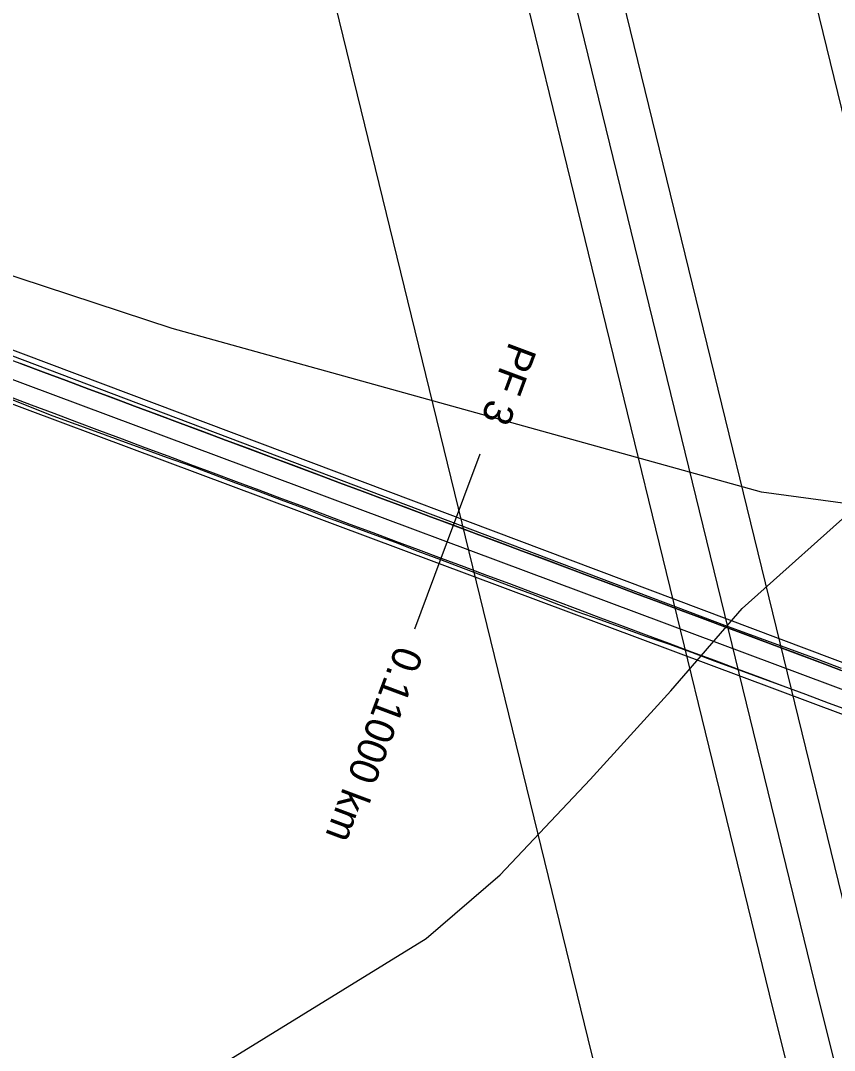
# Model space of a CAD drawing. Extents: x -555887 to -552101, y -1100251 to -1096546.
# Drawn here: x -553613.1 to -553543.4, y -1097330.6 to -1097242.4 of the extents above; entities that cross this region are included whole.
import ezdxf

# ---------------------------------------------------------------- set-up
doc = ezdxf.new("R2010")
doc.units = 0
for name, color, linetype in [('07_OCH_P A POPISY TI', 7, 'Continuous'), ('07_PLYNOVOD', 7, 'Continuous'), ('PARCELY_cesty', 7, 'Continuous'), ('POLYGONY_SITUACE_PF', 7, 'Continuous'), ('POLYGONY_SITUACE_PF_POPISY', 7, 'Continuous'), ('POLYGONY_SITUACE_PO', 7, 'Continuous'), ('vrstevnice', 7, 'Continuous'), ('ZSST', 7, 'Continuous')]:
    doc.layers.add(name, color=color, linetype=linetype)

msp = doc.modelspace()

# ---------------------------------------------------------------- linework, layer by layer
at = {"layer": '07_OCH_P A POPISY TI'}
for points in [[(-553574.217, -1097120.442), (-553565.588, -1097155.535), (-553546.885, -1097232.999), (-553525.624, -1097320.013), (-553504.501, -1097404.573), (-553504.455, -1097404.754), (-553494.227, -1097444.768), (-553477.771, -1097515.856), (-553477.697, -1097516.109), (-553477.381, -1097517.195), (-553476.998, -1097519.425), (-553476.868, -1097521.684), (-553476.994, -1097523.943), (-553477.184, -1097525.058), (-553488.78, -1097593.146), (-553503.72, -1097682.074)], [(-553589.763, -1097124.224), (-553581.134, -1097159.323), (-553562.433, -1097236.776), (-553541.157, -1097323.851), (-553520.012, -1097408.499), (-553519.955, -1097408.722), (-553509.773, -1097448.554), (-553493.258, -1097519.899), (-553493.059, -1097520.582), (-553492.932, -1097521.018), (-553492.88, -1097521.924), (-553492.957, -1097522.372), (-553504.556, -1097590.477), (-553519.48, -1097679.311)], [(-553527.36, -1097677.929), (-553512.444, -1097589.143), (-553500.998, -1097521.936), (-553501.002, -1097521.921), (-553517.547, -1097450.446), (-553527.705, -1097410.706), (-553527.768, -1097410.461), (-553548.923, -1097325.769), (-553570.207, -1097238.664), (-553588.906, -1097161.217), (-553597.537, -1097126.116)], [(-553543.12, -1097675.166), (-553528.22, -1097586.474), (-553517.31, -1097522.417), (-553533.093, -1097454.232), (-553543.205, -1097414.674), (-553543.279, -1097414.387), (-553564.456, -1097329.607), (-553585.755, -1097242.441), (-553604.452, -1097165.005), (-553613.083, -1097129.898)]]:
    msp.add_lwpolyline(points, dxfattribs=at)
at = {"layer": '07_PLYNOVOD'}
msp.add_lwpolyline([(-553585.25, -1098028.34), (-553568.13, -1097932.52), (-553553.96, -1097851.86), (-553539.25, -1097765.27), (-553523.42, -1097678.62), (-553508.5, -1097589.81), (-553496.9, -1097521.7), (-553497.13, -1097520.91), (-553513.66, -1097449.5), (-553523.83, -1097409.714), (-553523.89, -1097409.48), (-553545.04, -1097324.81), (-553566.32, -1097237.72), (-553585.02, -1097160.27), (-553593.65, -1097125.17), (-553614.64, -1097037.99), (-553634.86, -1096953.32), (-553647.662, -1096902.456)], dxfattribs=at)
at = {"layer": 'PARCELY_cesty'}
msp.add_line((-553673.4, -1097248.15), (-553478.332, -1097321.582), dxfattribs=at)
msp.add_lwpolyline([(-553665.731, -1097263.939), (-553661.91, -1097259.75), (-553656.336, -1097259.353), (-553478.346, -1097325.848)], dxfattribs=at)
at = {"layer": 'POLYGONY_SITUACE_PF'}
for p, q in [((-553573.729, -1097279.527), (-553576.529, -1097287.021)), ((-553576.529, -1097287.021), (-553579.33, -1097294.515))]:
    msp.add_line(p, q, dxfattribs=at)
at = {"layer": 'POLYGONY_SITUACE_PO'}
for p, q in [((-553675.709, -1097247.696), (-553552.545, -1097294.259)), ((-553679.807, -1097248.45), (-553478.542, -1097323.639)), ((-553673.735, -1097249.093), (-553501.847, -1097313.329)), ((-553613.083, -1097271.759), (-553611.132, -1097272.489)), ((-553611.132, -1097272.489), (-553613.083, -1097271.759)), ((-553611.132, -1097272.489), (-553609.18, -1097273.218)), ((-553609.18, -1097273.218), (-553611.132, -1097272.489)), ((-553609.18, -1097273.218), (-553607.229, -1097273.947)), ((-553607.229, -1097273.947), (-553609.18, -1097273.218)), ((-553607.229, -1097273.947), (-553605.277, -1097274.676)), ((-553605.277, -1097274.676), (-553607.229, -1097273.947)), ((-553614.185, -1097274.707), (-553612.249, -1097275.478)), ((-553614.133, -1097274.569), (-553612.182, -1097275.299)), ((-553614.133, -1097274.569), (-553612.182, -1097275.299)), ((-553605.277, -1097274.676), (-553603.325, -1097275.406)), ((-553603.325, -1097275.406), (-553605.277, -1097274.676)), ((-553612.249, -1097275.478), (-553610.307, -1097276.234)), ((-553612.182, -1097275.299), (-553610.23, -1097276.028)), ((-553612.182, -1097275.299), (-553610.23, -1097276.028)), ((-553603.325, -1097275.406), (-553601.374, -1097276.135)), ((-553601.374, -1097276.135), (-553603.325, -1097275.406)), ((-553610.307, -1097276.234), (-553608.349, -1097276.947)), ((-553610.23, -1097276.028), (-553608.279, -1097276.757)), ((-553610.23, -1097276.028), (-553608.279, -1097276.757)), ((-553601.374, -1097276.135), (-553599.422, -1097276.864)), ((-553599.422, -1097276.864), (-553601.374, -1097276.135)), ((-553608.349, -1097276.947), (-553606.392, -1097277.659)), ((-553608.279, -1097276.757), (-553606.327, -1097277.487)), ((-553608.279, -1097276.757), (-553606.327, -1097277.487)), ((-553606.327, -1097277.487), (-553604.376, -1097278.216)), ((-553606.327, -1097277.487), (-553604.376, -1097278.216)), ((-553599.422, -1097276.864), (-553597.471, -1097277.594)), ((-553597.471, -1097277.594), (-553599.422, -1097276.864)), ((-553606.392, -1097277.659), (-553604.436, -1097278.376)), ((-553604.436, -1097278.376), (-553602.48, -1097279.093)), ((-553604.376, -1097278.216), (-553602.424, -1097278.945)), ((-553604.376, -1097278.216), (-553602.424, -1097278.945)), ((-553597.471, -1097277.594), (-553595.519, -1097278.323)), ((-553595.519, -1097278.323), (-553597.471, -1097277.594)), ((-553595.519, -1097278.323), (-553593.568, -1097279.052)), ((-553593.568, -1097279.052), (-553595.519, -1097278.323)), ((-553602.48, -1097279.093), (-553600.523, -1097279.808)), ((-553602.424, -1097278.945), (-553600.473, -1097279.675)), ((-553602.424, -1097278.945), (-553600.473, -1097279.675)), ((-553593.568, -1097279.052), (-553591.616, -1097279.782)), ((-553591.616, -1097279.782), (-553593.568, -1097279.052)), ((-553600.523, -1097279.808), (-553598.553, -1097280.49)), ((-553600.473, -1097279.675), (-553598.521, -1097280.404)), ((-553600.473, -1097279.675), (-553598.521, -1097280.404)), ((-553591.616, -1097279.782), (-553589.665, -1097280.511)), ((-553589.665, -1097280.511), (-553591.616, -1097279.782)), ((-553598.553, -1097280.49), (-553596.608, -1097281.236)), ((-553598.521, -1097280.404), (-553596.57, -1097281.133)), ((-553598.521, -1097280.404), (-553596.57, -1097281.133)), ((-553589.665, -1097280.511), (-553587.713, -1097281.24)), ((-553587.713, -1097281.24), (-553589.665, -1097280.511)), ((-553596.608, -1097281.236), (-553594.658, -1097281.968)), ((-553596.57, -1097281.133), (-553594.618, -1097281.862)), ((-553596.57, -1097281.133), (-553594.618, -1097281.862)), ((-553594.618, -1097281.862), (-553592.667, -1097282.592)), ((-553594.618, -1097281.862), (-553592.667, -1097282.592)), ((-553587.713, -1097281.24), (-553585.762, -1097281.969)), ((-553585.762, -1097281.969), (-553587.713, -1097281.24)), ((-553594.658, -1097281.968), (-553592.704, -1097282.692)), ((-553592.704, -1097282.692), (-553590.756, -1097283.43)), ((-553592.667, -1097282.592), (-553590.715, -1097283.321)), ((-553592.667, -1097282.592), (-553590.715, -1097283.321)), ((-553585.762, -1097281.969), (-553583.81, -1097282.699)), ((-553583.81, -1097282.699), (-553585.762, -1097281.969)), ((-553583.81, -1097282.699), (-553581.859, -1097283.428)), ((-553581.859, -1097283.428), (-553583.81, -1097282.699)), ((-553590.756, -1097283.43), (-553588.804, -1097284.158)), ((-553590.715, -1097283.321), (-553588.764, -1097284.05)), ((-553590.715, -1097283.321), (-553588.764, -1097284.05)), ((-553581.859, -1097283.428), (-553579.907, -1097284.157)), ((-553579.907, -1097284.157), (-553581.859, -1097283.428)), ((-553588.804, -1097284.158), (-553586.862, -1097284.913)), ((-553588.764, -1097284.05), (-553586.812, -1097284.78)), ((-553588.764, -1097284.05), (-553586.812, -1097284.78)), ((-553579.907, -1097284.157), (-553577.956, -1097284.887)), ((-553577.956, -1097284.887), (-553579.907, -1097284.157)), ((-553586.862, -1097284.913), (-553584.908, -1097285.636)), ((-553586.812, -1097284.78), (-553584.861, -1097285.509)), ((-553586.812, -1097284.78), (-553584.861, -1097285.509)), ((-553577.956, -1097284.887), (-553576.004, -1097285.616)), ((-553576.004, -1097285.616), (-553577.956, -1097284.887)), ((-553584.908, -1097285.636), (-553582.951, -1097286.35)), ((-553584.861, -1097285.509), (-553582.909, -1097286.238)), ((-553584.861, -1097285.509), (-553582.909, -1097286.238)), ((-553582.909, -1097286.238), (-553580.958, -1097286.967)), ((-553582.909, -1097286.238), (-553580.958, -1097286.967)), ((-553576.004, -1097285.616), (-553574.053, -1097286.345)), ((-553574.053, -1097286.345), (-553576.004, -1097285.616)), ((-553582.951, -1097286.35), (-553580.995, -1097287.067)), ((-553580.995, -1097287.067), (-553579.057, -1097287.832)), ((-553580.958, -1097286.967), (-553579.006, -1097287.697)), ((-553580.958, -1097286.967), (-553579.006, -1097287.697)), ((-553574.053, -1097286.345), (-553572.101, -1097287.074)), ((-553572.101, -1097287.074), (-553574.053, -1097286.345)), ((-553572.101, -1097287.074), (-553570.15, -1097287.804)), ((-553570.15, -1097287.804), (-553572.101, -1097287.074)), ((-553579.057, -1097287.832), (-553577.104, -1097288.558)), ((-553579.006, -1097287.697), (-553577.054, -1097288.426)), ((-553579.006, -1097287.697), (-553577.054, -1097288.426)), ((-553570.15, -1097287.804), (-553568.198, -1097288.533)), ((-553568.198, -1097288.533), (-553570.15, -1097287.804)), ((-553577.104, -1097288.558), (-553575.151, -1097289.283)), ((-553577.054, -1097288.426), (-553575.103, -1097289.155)), ((-553577.054, -1097288.426), (-553575.103, -1097289.155)), ((-553568.198, -1097288.533), (-553566.247, -1097289.262)), ((-553566.247, -1097289.262), (-553568.198, -1097288.533)), ((-553575.151, -1097289.283), (-553573.203, -1097290.022)), ((-553575.103, -1097289.155), (-553573.151, -1097289.885)), ((-553575.103, -1097289.155), (-553573.151, -1097289.885)), ((-553566.247, -1097289.262), (-553564.295, -1097289.992)), ((-553564.295, -1097289.992), (-553566.247, -1097289.262)), ((-553573.203, -1097290.022), (-553571.263, -1097290.783)), ((-553573.151, -1097289.885), (-553571.2, -1097290.614)), ((-553573.151, -1097289.885), (-553571.2, -1097290.614)), ((-553571.2, -1097290.614), (-553569.248, -1097291.343)), ((-553571.2, -1097290.614), (-553569.248, -1097291.343)), ((-553564.295, -1097289.992), (-553562.344, -1097290.721)), ((-553562.344, -1097290.721), (-553564.295, -1097289.992)), ((-553562.344, -1097290.721), (-553560.392, -1097291.45)), ((-553560.392, -1097291.45), (-553562.344, -1097290.721)), ((-553571.263, -1097290.783), (-553569.304, -1097291.492)), ((-553569.304, -1097291.492), (-553567.365, -1097292.256)), ((-553569.248, -1097291.343), (-553567.297, -1097292.073)), ((-553569.248, -1097291.343), (-553567.297, -1097292.073)), ((-553560.392, -1097291.45), (-553558.441, -1097292.18)), ((-553558.441, -1097292.18), (-553560.392, -1097291.45)), ((-553567.365, -1097292.256), (-553565.422, -1097293.008)), ((-553567.297, -1097292.073), (-553565.345, -1097292.802)), ((-553567.297, -1097292.073), (-553565.345, -1097292.802)), ((-553558.441, -1097292.18), (-553556.489, -1097292.909)), ((-553556.489, -1097292.909), (-553558.441, -1097292.18)), ((-553565.422, -1097293.008), (-553563.455, -1097293.695)), ((-553565.345, -1097292.802), (-553563.394, -1097293.531)), ((-553565.345, -1097292.802), (-553563.394, -1097293.531)), ((-553556.489, -1097292.909), (-553554.538, -1097293.638)), ((-553554.538, -1097293.638), (-553556.489, -1097292.909)), ((-553563.455, -1097293.695), (-553561.495, -1097294.401)), ((-553563.394, -1097293.531), (-553561.442, -1097294.26)), ((-553563.394, -1097293.531), (-553561.442, -1097294.26)), ((-553561.442, -1097294.26), (-553559.491, -1097294.99)), ((-553561.442, -1097294.26), (-553559.491, -1097294.99)), ((-553554.538, -1097293.638), (-553552.586, -1097294.367)), ((-553552.586, -1097294.367), (-553554.538, -1097293.638)), ((-553552.545, -1097294.259), (-553550.586, -1097294.966)), ((-553561.495, -1097294.401), (-553559.541, -1097295.124)), ((-553559.541, -1097295.124), (-553557.564, -1097295.786)), ((-553559.491, -1097294.99), (-553557.539, -1097295.719)), ((-553559.491, -1097294.99), (-553557.539, -1097295.719)), ((-553552.586, -1097294.367), (-553550.635, -1097295.097)), ((-553550.635, -1097295.097), (-553552.586, -1097294.367)), ((-553550.635, -1097295.097), (-553548.683, -1097295.826)), ((-553548.683, -1097295.826), (-553550.635, -1097295.097)), ((-553550.586, -1097294.966), (-553548.628, -1097295.679)), ((-553557.564, -1097295.786), (-553555.606, -1097296.496)), ((-553557.539, -1097295.719), (-553555.588, -1097296.448)), ((-553557.539, -1097295.719), (-553555.588, -1097296.448)), ((-553548.683, -1097295.826), (-553546.732, -1097296.555)), ((-553546.732, -1097296.555), (-553548.683, -1097295.826)), ((-553548.628, -1097295.679), (-553546.671, -1097296.393)), ((-553555.606, -1097296.496), (-553553.652, -1097297.219)), ((-553555.588, -1097296.448), (-553553.636, -1097297.178)), ((-553555.588, -1097296.448), (-553553.636, -1097297.178)), ((-553546.732, -1097296.555), (-553544.78, -1097297.285)), ((-553544.78, -1097297.285), (-553546.732, -1097296.555)), ((-553546.671, -1097296.393), (-553544.714, -1097297.109)), ((-553553.652, -1097297.219), (-553551.693, -1097297.928)), ((-553553.636, -1097297.178), (-553551.685, -1097297.907)), ((-553553.636, -1097297.178), (-553551.685, -1097297.907)), ((-553544.78, -1097297.285), (-553542.829, -1097298.014)), ((-553542.829, -1097298.014), (-553544.78, -1097297.285)), ((-553544.714, -1097297.109), (-553542.767, -1097297.849)), ((-553551.693, -1097297.928), (-553549.736, -1097298.643)), ((-553551.685, -1097297.907), (-553549.733, -1097298.636)), ((-553551.685, -1097297.907), (-553549.733, -1097298.636)), ((-553549.736, -1097298.643), (-553547.782, -1097299.365)), ((-553549.733, -1097298.636), (-553547.782, -1097299.365)), ((-553549.733, -1097298.636), (-553547.782, -1097299.365)), ((-553547.782, -1097299.365), (-553545.83, -1097300.095)), ((-553547.782, -1097299.365), (-553545.83, -1097300.095)), ((-553547.782, -1097299.365), (-553547.782, -1097299.365)), ((-553547.782, -1097299.365), (-553545.83, -1097300.095)), ((-553545.83, -1097300.095), (-553543.879, -1097300.824)), ((-553545.83, -1097300.095), (-553543.879, -1097300.824)), ((-553545.83, -1097300.095), (-553543.879, -1097300.824)), ((-553543.879, -1097300.824), (-553541.927, -1097301.553)), ((-553543.879, -1097300.824), (-553541.927, -1097301.553)), ((-553543.879, -1097300.824), (-553541.927, -1097301.553))]:
    msp.add_line(p, q, dxfattribs=at)
at = {"layer": 'vrstevnice'}
msp.add_lwpolyline([(-553631.168, -1097353.541), (-553578.331, -1097321.003), (-553572.003, -1097315.556), (-553564.293, -1097307.395), (-553557.364, -1097299.798), (-553551.25, -1097292.743), (-553540.788, -1097283.382), (-553533.451, -1097277.684), (-553526.794, -1097273.886), (-553520.68, -1097272.665), (-553512.935, -1097273.479), (-553507.5, -1097275.785), (-553502.202, -1097279.855), (-553498.941, -1097284.196), (-553494.05, -1097293.829), (-553494.05, -1097295.05), (-553492.555, -1097301.833), (-553491.468, -1097311.33), (-553491.196, -1097327.61), (-553493.914, -1097341.041)], dxfattribs=at)
at = {"layer": 'ZSST'}
for points in [[(-553600.1, -1097268.75), (-553657.15, -1097250.01), (-553728.97, -1097225.8), (-553769.71, -1097212.97), (-553838.99, -1097189.46), (-553892.69, -1097170.63), (-553926.55, -1097160.61)], [(-553519.85, -1097304.5), (-553517.47, -1097287.12), (-553549.61, -1097282.79), (-553600.1, -1097268.75)]]:
    msp.add_lwpolyline(points, dxfattribs=at)

# ---------------------------------------------------------------- texts
at = {"layer": '07_PLYNOVOD'}
msp.add_text('plynovod VTL DN 150', height=15, rotation=282.75467, dxfattribs=at).set_placement((-553570.024, -1097101.125))
at = {"layer": 'POLYGONY_SITUACE_PF_POPISY'}
for s, p in [('PF 3', (-553571.165, -1097269.81)), ('0.11000 km', (-553580.88, -1097295.807))]:
    msp.add_text(s, height=2.5, rotation=249.50895, dxfattribs=at).set_placement(p)

doc.saveas('drawing.dxf')
